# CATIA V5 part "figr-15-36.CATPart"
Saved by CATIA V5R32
Part number: Part1
Bounding box of the stored display mesh (mm): x -63.331 to 107.433, y -39.139 to 39.139, z 0 to 70.926
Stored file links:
  D:\PROJECTS\Project 2022\CATIA V5 6R 2022\Resources\Part Files\c15_catia_v5_6r2022_prt\figr-15-36.CATPart
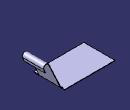
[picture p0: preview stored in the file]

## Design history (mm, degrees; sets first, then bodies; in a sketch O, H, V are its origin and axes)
SheetMetalParameters1: Thickness 1, BendRadius 2, KFactor 0.400515 {= log(min(100,max(20*SheetMetalParameters1.BendRadius,SheetMetalParameters1.Thickness)/SheetMetalParameters1.Thickness))/log(100)/2}, ReliefRadialLength 1, ReliefAxialLength 2, MinimumBendRadius 0
Body1 (main body)
  Sketch1 on xy-plane, origin (0, 0, 0), H (1, 0, 0), V (0, 1, 0)
    line L1 (-63.3311, 39.1393) -> (63.3311, 39.1393)
    line L2 (63.3311, 39.1393) -> (63.3311, -39.1393)
    line L3 (63.3311, -39.1393) -> (-63.3311, -39.1393)
    line L4 (-63.3311, -39.1393) -> (-63.3311, 39.1393)
    horizontal: L1 H, L3 H
    vertical: L2 V, L4 V
    symmetry: L4 L2 V, L1 L3 H
  Wall1: Thickness 1, Profile Sketch1
  d_NewWallOnEdge1: NewWallOnEdge_Edge edge [face of Wall1 | face of Wall1], NewWallOnEdge_Length 67, NewWallOnEdge_HeightLimitOffset 0, NewWallOnEdge_WidthOffset1 -16, NewWallOnEdge_WidthOffset2 -9, NewWallOnEdge_Angle 115, NewWallOnEdge_BendRadiusValue 2 {= SheetMetalParameters1.BendRadius}, NewWallOnEdge_BendTable SheetMetalParameters1, KFacteur 0.400515 {= log(min(100,max(20*d_NewWallOnEdge1.Radius,SheetMetalParameters1.Thickness)/SheetMetalParameters1.Thickness))/log(100)/2}
  Flange1: Angle 4, Length 10, Radius 6, KFacteur 0.5 {= log(min(100,max(20*Flange1.Radius,SheetMetalParameters1.Thickness)/SheetMetalParameters1.Thickness))/log(100)/2}, Guide edge [face of d_NewWallOnEdge1 | face of d_NewWallOnEdge1]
